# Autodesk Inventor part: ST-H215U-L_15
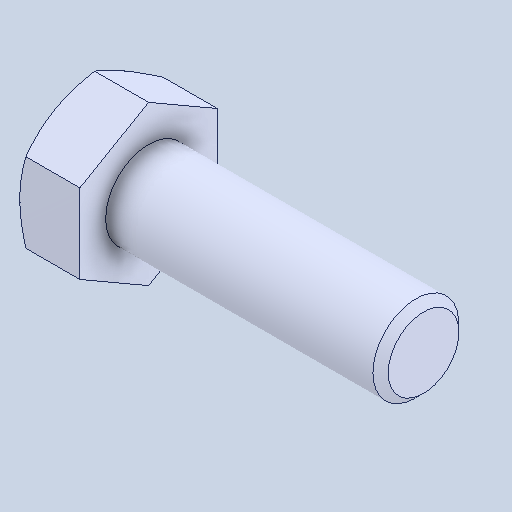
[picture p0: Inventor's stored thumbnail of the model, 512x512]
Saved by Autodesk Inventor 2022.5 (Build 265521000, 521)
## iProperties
Created: 2024-07
Part Number: ST-H215U-L_15
Material: 一般
Document SubType Name: Modeling
Designer: ImaoCorp
Density: 1 g/cm^3
Appearance: 既定
Author: ImaoCorp
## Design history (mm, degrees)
feature "ST-H215U-L_15"
node "ソリッド1"
